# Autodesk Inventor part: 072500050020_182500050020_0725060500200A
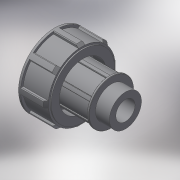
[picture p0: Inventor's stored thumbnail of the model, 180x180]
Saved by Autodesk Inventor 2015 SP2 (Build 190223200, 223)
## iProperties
Created: 2017-04
Part Number: 072500050020_182500050020_0725060500200A
Material: Generic
Description: PLASSON THREADED ADAPTOR 50-2"
Document SubType Name: Modeling
Designer: KIM
Density: 1 g/cm^3
Appearance: Default
Author: KIM
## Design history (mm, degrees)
derived "07250.ipt"
feature "Solid1::07250.ipt"
tag "TaggingFeature1"
body "Solid1"
other parameters: "d1" = 59.614, "d2" = 107, "d3" = 27, "d6" = 96, "d7" = 89.28, "d8" = 76.8, "d10" = 71.5368, "d12" = 35.7684, "d13" = 41.7298, "d14" = 31.05, "d15" = 72, "d16" = 3.21, "d17" = 42.8, "d18" = 27, "d19" = 32.4, "d24" = 11.9228, "d25" = 5.9614, "d27" = 0, "d28" = 4.76912, "d31" = 1.19228, "d35" = 360 deg, "d41" = 29.337, "d56" = 55, "d57" = 5, "d58" = 2.5, "d60" = 0, "d61" = 0.59614, "d64" = 0.59614, "d68" = 360 deg, "R_" = 59.614, "E_" = 96, "H_" = 107, "l_2" = 27
